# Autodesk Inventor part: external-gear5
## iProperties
Author: Ole Germer
Shininess: 64.0
Angle Display Precision: 2
Document Length Units: 11272
Document Angle Units: 11286
Document Time Units: 11279
Document Mass Units: 11290
Document Length Units Precision: 3
Document Angle Units Precision: 2
Compacted: True
PropertySet Name: _Private Model Information
Created: 2002-02
Part Number: external-gear5
Material: ASTM A36 HRS
Document SubType Name: Modeling
Designer: Ole Germer
Control State: 0
Master: False
Checked Out: False
PropertySet Name: Design Tracking Control
Density: 0.0
Volumn: 0.0
Area: 0.0
PropertySet Name: Model Information
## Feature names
1. Extrusion1
2. Extrusion2
3. Fillet1
4. Mirror1
5. Circular Pattern1
